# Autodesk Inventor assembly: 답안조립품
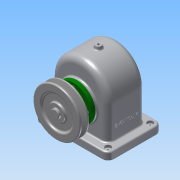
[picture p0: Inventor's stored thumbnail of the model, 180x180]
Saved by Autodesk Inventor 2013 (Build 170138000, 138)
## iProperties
Created: 2016-10
Part Number: 답안조립품
Document SubType Name: Assembly
Designer: user
Author: user
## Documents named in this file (15)
- C:\Users\user\Desktop\461008V1032\답안조립품.iam
- C:\Users\user\Desktop\461008V1032\본체.ipt
- C:\Users\user\Desktop\461008V1032\V-벨트풀리.ipt
- C:\Users\user\Desktop\461008V1032\뒤커버.ipt
- C:\Users\user\Desktop\461008V1032\멈춤나사 - M4x10.ipt
- C:\Users\user\Desktop\461008V1032\베어링 6203.ipt
- C:\Users\user\Desktop\461008V1032\볼트 M3 x 8.ipt
- C:\Users\user\Desktop\461008V1032\볼트 M3 x 10.ipt
- C:\Users\user\Desktop\461008V1032\부시.ipt
- C:\Users\user\Desktop\461008V1032\스퍼기어.ipt
- C:\Users\user\Desktop\461008V1032\앞커버.ipt
- C:\Users\user\Desktop\461008V1032\오일씰 28 40 8.ipt
- C:\Users\user\Desktop\461008V1032\축.ipt
- C:\Users\user\Desktop\461008V1032\키 - 5 x 5 x 18.ipt
- C:\Users\user\Desktop\461008V1032\키 - 6 x 6 x 22.ipt
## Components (9 placed, 3 different names)
1. V-벨트풀리:1 — 각도:4
2. ISO 4762 M3 x 8:1
3. ISO 4762 M3 x 8:2
4. ISO 4762 M3 x 8:3
5. ISO 4762 M3 x 8:4
6. ISO 4762 M3 x 10:1
7. ISO 4762 M3 x 10:2
8. ISO 4762 M3 x 10:3
9. ISO 4762 M3 x 10:4
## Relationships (1: Angle 1)
- 각도:4 [Angle]: V-벨트풀리:1
